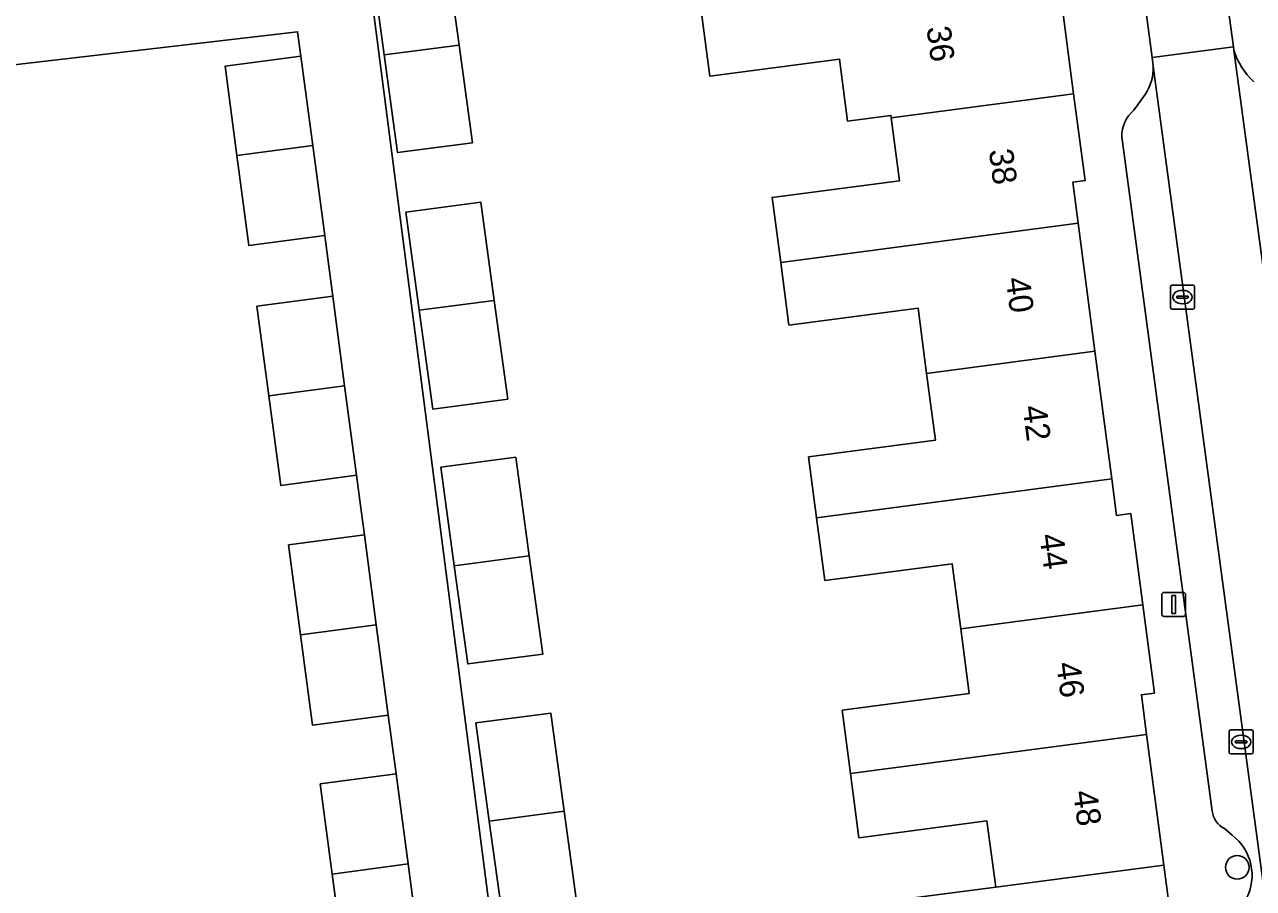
# Model space of a CAD drawing. Extents: x 163147 to 163550, y 380933 to 381639.
# Drawn here: x 163359.7 to 163410.6, y 381335.7 to 381371.5 of the extents above; entities that cross this region are included whole.
import ezdxf

# ---------------------------------------------------------------- set-up
doc = ezdxf.new("R2010")
doc.units = 0
for name, color, linetype in [('IMGEO_Boom', 7, 'Continuous'), ('IMGEO_Erf', 7, 'Continuous'), ('IMGEO_Kolk', 7, 'Continuous'), ('IMGEO_Lichtmast', 7, 'Continuous'), ('IMGEO_Pand', 7, 'Continuous'), ('IMGEO_Pand_nummerreeks', 7, 'Continuous'), ('IMGEO_Parkeervlak_open', 7, 'Continuous'), ('IMGEO_Rijbaan_lokaal_open', 7, 'Continuous'), ('IMGEO_Voetpad_open', 7, 'Continuous')]:
    doc.layers.add(name, color=color, linetype=linetype)

msp = doc.modelspace()

# ---------------------------------------------------------------- linework, layer by layer
at = {"layer": 'IMGEO_Boom'}
msp.add_circle((163409.946, 381336.541), 0.489, dxfattribs=at)
at = {"layer": 'IMGEO_Erf'}
for points in [[(163373.686, 381375.541), (163379.182, 381333.036)], [(163382.784, 381333.502), (163399.932, 381335.719), (163399.572, 381338.463), (163394.265, 381337.766), (163393.915, 381340.431), (163393.57, 381343.051), (163398.835, 381343.744), (163398.483, 381346.421), (163398.129, 381349.112), (163392.852, 381348.418), (163392.51, 381351.018), (163392.178, 381353.546), (163397.432, 381354.237), (163397.068, 381357.007), (163396.713, 381359.709), (163391.363, 381359.005), (163391.022, 381361.596), (163390.667, 381364.294), (163395.947, 381364.988), (163395.605, 381367.589), (163395.591, 381367.696), (163393.795, 381367.46), (163393.457, 381370.029), (163388.079, 381369.322), (163387.736, 381371.936)], [(163372.924, 381332.563), (163372.433, 381336.262), (163371.937, 381339.995), (163375.08, 381340.413), (163374.918, 381341.632), (163374.756, 381342.85), (163371.613, 381342.432), (163371.118, 381346.167), (163370.622, 381349.899), (163373.765, 381350.318), (163373.603, 381351.536), (163373.438, 381352.782), (163370.295, 381352.363), (163369.803, 381356.07), (163369.309, 381359.787), (163372.452, 381360.205), (163372.288, 381361.442), (163372.119, 381362.716), (163368.976, 381362.298), (163368.48, 381366.03), (163367.988, 381369.734), (163371.131, 381370.151), (163370.998, 381371.159), (163352.337, 381368.984)]]:
    msp.add_lwpolyline(points, dxfattribs=at)
for points in [[(163377.694, 381370.61), (163378.249, 381366.564), (163375.142, 381366.154), (163374.587, 381370.2), (163374.056, 381374.068), (163377.161, 381374.494)], [(163379.146, 381360.028), (163379.707, 381355.941), (163376.6, 381355.53), (163376.039, 381359.618), (163375.481, 381363.683), (163378.588, 381364.093)], [(163380.598, 381349.444), (163381.155, 381345.378), (163378.049, 381344.968), (163377.491, 381349.033), (163376.93, 381353.119), (163380.037, 381353.53)], [(163378.942, 381338.454), (163378.383, 381342.525), (163381.49, 381342.935), (163382.049, 381338.865), (163382.685, 381334.223), (163379.58, 381333.797)]]:
    msp.add_lwpolyline(points, close=True, dxfattribs=at)
at = {"layer": 'IMGEO_Kolk'}
for p, q in [((163407.177, 381359.739), (163407.177, 381360.591)), ((163407.252, 381360.665), (163408.104, 381360.665)), ((163407.665, 381360.445), (163407.69, 381360.445)), ((163408.178, 381360.591), (163408.178, 381359.739)), ((163407.436, 381360.159), (163407.436, 381360.171)), ((163407.874, 381360.122), (163407.476, 381360.122)), ((163407.479, 381360.208), (163407.877, 381360.208)), ((163407.688, 381359.885), (163407.663, 381359.885)), ((163407.92, 381360.171), (163407.92, 381360.159)), ((163408.104, 381359.665), (163407.252, 381359.665)), ((163409.606, 381341.311), (163409.606, 381342.163)), ((163409.681, 381342.237), (163410.533, 381342.237)), ((163410.094, 381342.017), (163410.119, 381342.017)), ((163410.607, 381342.163), (163410.607, 381341.311)), ((163409.865, 381341.731), (163409.865, 381341.743)), ((163410.303, 381341.694), (163409.905, 381341.694)), ((163409.908, 381341.78), (163410.306, 381341.78)), ((163410.117, 381341.457), (163410.092, 381341.457)), ((163410.349, 381341.743), (163410.349, 381341.731)), ((163410.533, 381341.237), (163409.681, 381341.237))]:
    msp.add_line(p, q, dxfattribs=at)
for points in [[(163407.177, 381359.739), (163407.177, 381360.591)], [(163407.252, 381360.665), (163408.104, 381360.665)], [(163408.178, 381360.591), (163408.178, 381359.739)], [(163408.104, 381359.665), (163407.252, 381359.665)], [(163409.606, 381341.311), (163409.606, 381342.163)], [(163409.681, 381342.237), (163410.533, 381342.237)], [(163410.607, 381342.163), (163410.607, 381341.311)], [(163410.533, 381341.237), (163409.681, 381341.237)]]:
    msp.add_lwpolyline(points, dxfattribs=at)
for centre, radius, start, end in [((163407.254, 381360.589), 0.0765, 91.552, 178.448), ((163407.254, 381360.589), 0.0765, 91.552, 178.448), ((163408.102, 381360.589), 0.0765, 1.552, 88.448), ((163408.102, 381360.589), 0.0765, 1.552, 88.448), ((163407.254, 381359.741), 0.0765, 181.552, 268.448), ((163407.254, 381359.741), 0.0765, 181.552, 268.448), ((163407.476, 381360.168), 0.0403, 85.8775, 175.7526), ((163407.473, 381360.158), 0.0366, 178.938, 274.7102), ((163407.877, 381360.165), 0.043, 264.8664, 352.4533), ((163407.881, 381360.17), 0.0386, 1.7309, 96.639), ((163408.102, 381359.741), 0.0765, 271.552, 358.448), ((163408.102, 381359.741), 0.0765, 271.552, 358.448), ((163409.683, 381342.161), 0.0765, 91.552, 178.448), ((163409.683, 381342.161), 0.0765, 91.552, 178.448), ((163410.531, 381342.161), 0.0765, 1.552, 88.448), ((163410.531, 381342.161), 0.0765, 1.552, 88.448), ((163409.905, 381341.74), 0.0403, 85.8775, 175.7526), ((163409.902, 381341.73), 0.0366, 178.938, 274.7102), ((163410.306, 381341.737), 0.043, 264.8664, 352.4533), ((163410.31, 381341.742), 0.0386, 1.7309, 96.639), ((163409.683, 381341.313), 0.0765, 181.552, 268.448), ((163409.683, 381341.313), 0.0765, 181.552, 268.448), ((163410.531, 381341.313), 0.0765, 271.552, 358.448), ((163410.531, 381341.313), 0.0765, 271.552, 358.448)]:
    msp.add_arc(centre, radius, start, end, dxfattribs=at)
for centre, major_axis, ratio, start_param, end_param in [((163407.664, 381360.165), (-0.387, 0.002), 0.722429, 4.712389, 7.853982), ((163407.689, 381360.165), (-0.39, 0.002), 0.717154, 1.570796, 4.712389), ((163410.093, 381341.737), (-0.387, 0.002), 0.722429, 4.712389, 7.853982), ((163410.118, 381341.737), (-0.39, 0.002), 0.717154, 1.570796, 4.712389)]:
    msp.add_ellipse(centre, major_axis=major_axis, ratio=ratio, start_param=start_param, end_param=end_param, dxfattribs=at)
at = {"layer": 'IMGEO_Lichtmast'}
for p, q in [((163406.816, 381347.034), (163406.816, 381347.834)), ((163406.816, 381347.834), (163406.816, 381347.034)), ((163406.916, 381347.934), (163407.706, 381347.934)), ((163407.706, 381347.934), (163406.916, 381347.934)), ((163407.806, 381347.834), (163407.806, 381347.034)), ((163407.806, 381347.034), (163407.806, 381347.834)), ((163407.706, 381346.934), (163406.916, 381346.934)), ((163406.916, 381346.934), (163407.706, 381346.934))]:
    msp.add_line(p, q, dxfattribs=at)
msp.add_lwpolyline([(163407.236, 381347.809), (163407.386, 381347.809), (163407.386, 381347.059), (163407.236, 381347.059), (163407.236, 381347.809)], dxfattribs=at)
for centre, start, end in [((163406.916, 381347.834), 90, 180), ((163406.916, 381347.834), 90, 180), ((163407.706, 381347.834), 0, 90), ((163407.706, 381347.834), 360, 90), ((163406.916, 381347.034), 180, 270), ((163406.916, 381347.034), 180, 270), ((163407.706, 381347.034), 270, 0), ((163407.706, 381347.034), 270, 0)]:
    msp.add_arc(centre, 0.1, start, end, dxfattribs=at)
at = {"layer": 'IMGEO_Pand'}
for points in [[(163374.587, 381370.2), (163377.694, 381370.61), (163377.161, 381374.494), (163374.056, 381374.068)], [(163387.736, 381371.936), (163388.079, 381369.322), (163393.457, 381370.029), (163393.795, 381367.46), (163395.591, 381367.696), (163395.605, 381367.589), (163403.164, 381368.587), (163402.674, 381372.311), (163400.282, 381371.997), (163400.076, 381373.565)], [(163377.694, 381370.61), (163374.587, 381370.2), (163375.142, 381366.154), (163378.249, 381366.564)], [(163371.131, 381370.151), (163367.988, 381369.734), (163368.48, 381366.03), (163371.623, 381366.449)], [(163391.022, 381361.596), (163403.353, 381363.224), (163403.129, 381364.925), (163403.637, 381364.992), (163403.164, 381368.587), (163395.605, 381367.589), (163395.947, 381364.988), (163390.667, 381364.294)], [(163371.623, 381366.449), (163368.48, 381366.03), (163368.976, 381362.298), (163372.119, 381362.716)], [(163376.039, 381359.618), (163379.146, 381360.028), (163378.588, 381364.093), (163375.481, 381363.683)], [(163404.049, 381357.929), (163403.353, 381363.224), (163391.022, 381361.596), (163391.363, 381359.005), (163396.713, 381359.709), (163397.068, 381357.007)], [(163372.452, 381360.205), (163369.309, 381359.787), (163369.803, 381356.07), (163372.945, 381356.489)], [(163379.146, 381360.028), (163376.039, 381359.618), (163376.6, 381355.53), (163379.707, 381355.941)], [(163404.049, 381357.929), (163397.068, 381357.007), (163397.432, 381354.237), (163392.178, 381353.546), (163392.51, 381351.018), (163404.745, 381352.635)], [(163372.945, 381356.489), (163369.803, 381356.07), (163370.295, 381352.363), (163373.438, 381352.782)], [(163377.491, 381349.033), (163380.598, 381349.444), (163380.037, 381353.53), (163376.93, 381353.119)], [(163398.483, 381346.421), (163406.03, 381347.417), (163405.533, 381351.2), (163404.944, 381351.123), (163404.745, 381352.635), (163392.51, 381351.018), (163392.852, 381348.418), (163398.129, 381349.112)], [(163373.765, 381350.318), (163370.622, 381349.899), (163371.118, 381346.167), (163374.26, 381346.586)], [(163380.598, 381349.444), (163377.491, 381349.033), (163378.049, 381344.968), (163381.155, 381345.378)], [(163398.483, 381346.421), (163398.835, 381343.744), (163393.57, 381343.051), (163393.915, 381340.431), (163406.187, 381342.051), (163405.971, 381343.69), (163406.511, 381343.761), (163406.03, 381347.417)], [(163374.26, 381346.586), (163371.118, 381346.167), (163371.613, 381342.432), (163374.756, 381342.85)], [(163378.942, 381338.454), (163382.049, 381338.865), (163381.49, 381342.935), (163378.383, 381342.525)], [(163406.187, 381342.051), (163393.915, 381340.431), (163394.265, 381337.766), (163399.572, 381338.463), (163399.932, 381335.719), (163401.942, 381335.983), (163406.899, 381336.635)], [(163375.08, 381340.413), (163371.937, 381339.995), (163372.433, 381336.262), (163375.575, 381336.681)], [(163382.049, 381338.865), (163378.942, 381338.454), (163379.58, 381333.797), (163382.685, 381334.223)], [(163375.575, 381336.681), (163372.433, 381336.262), (163372.924, 381332.563), (163376.067, 381332.981)]]:
    msp.add_lwpolyline(points, close=True, dxfattribs=at)
at = {"layer": 'IMGEO_Parkeervlak_open'}
for points in [[(163409.808, 381370.393), (163417.023, 381316.959), (163417.13, 381316.166)], [(163412.274, 381317.247), (163413.073, 381316.642), (163413.31, 381316.453), (163413.709, 381315.897), (163413.628, 381316.496), (163406.464, 381369.736)], [(163406.129, 381368.567), (163405.657, 381367.909)], [(163405.157, 381366.806), (163408.907, 381338.869)], [(163409.412, 381338.143), (163409.728, 381337.875)]]:
    msp.add_lwpolyline(points, dxfattribs=at)
for centre, radius, start, end in [((163412.754, 381371.321), 3.089, 197.4756, 226.4724), ((163404.538, 381369.655), 1.927, 325.6202, 2.3984), ((163406.583, 381366.824), 1.426, 130.4883, 180.7413), ((163409.852, 381338.988), 0.952, 187.157, 242.4873), ((163408.485, 381336.213), 2.075, 331.7558, 53.1962)]:
    msp.add_arc(centre, radius, start, end, dxfattribs=at)
at = {"layer": 'IMGEO_Rijbaan_lokaal_open'}
for points in [[(163409.423, 381373.262), (163406.059, 381372.796), (163406.417, 381370.092), (163409.789, 381370.536)], [(163413.628, 381316.496), (163417.023, 381316.959), (163409.808, 381370.393), (163409.789, 381370.536), (163406.417, 381370.092), (163406.464, 381369.736)]]:
    msp.add_lwpolyline(points, close=True, dxfattribs=at)
at = {"layer": 'IMGEO_Voetpad_open'}
for points in [[(163379.182, 381333.036), (163373.686, 381375.541), (163392.431, 381378.067), (163394.407, 381378.327), (163399.364, 381378.978), (163399.159, 381380.49), (163394.204, 381379.827), (163392.162, 381379.554), (163386.909, 381378.852), (163376.889, 381377.496), (163373.783, 381377.077), (163373.493, 381377.038), (163367.775, 381419.465)], [(163408.974, 381376.615), (163409.423, 381373.262), (163409.789, 381370.536), (163409.808, 381370.393)], [(163406.464, 381369.736), (163406.417, 381370.092), (163406.059, 381372.796)], [(163402.674, 381372.311), (163403.164, 381368.587), (163403.637, 381364.992), (163403.129, 381364.925), (163403.353, 381363.224), (163404.049, 381357.929), (163404.745, 381352.635), (163404.944, 381351.123), (163405.533, 381351.2), (163406.03, 381347.417), (163406.511, 381343.761), (163405.971, 381343.69), (163406.187, 381342.051), (163406.899, 381336.635), (163407.09, 381335.16)], [(163352.337, 381368.984), (163370.998, 381371.159), (163371.131, 381370.151), (163371.623, 381366.449), (163372.119, 381362.716), (163372.288, 381361.442), (163372.452, 381360.205), (163372.945, 381356.489), (163373.438, 381352.782), (163373.603, 381351.536), (163373.765, 381350.318), (163374.26, 381346.586), (163374.756, 381342.85), (163374.918, 381341.632), (163375.08, 381340.413), (163375.575, 381336.681), (163376.067, 381332.981), (163376.227, 381331.775), (163376.249, 381331.604), (163355.814, 381328.888)], [(163405.657, 381367.909), (163406.129, 381368.567)], [(163408.907, 381338.869), (163405.157, 381366.806)], [(163409.728, 381337.875), (163409.412, 381338.143)], [(163407.09, 381335.16), (163406.899, 381336.635), (163401.942, 381335.983), (163399.932, 381335.719), (163382.784, 381333.502)]]:
    msp.add_lwpolyline(points, dxfattribs=at)
for centre, radius, start, end in [((163412.754, 381371.321), 3.089, 197.4756, 226.4724), ((163404.538, 381369.655), 1.927, 325.6202, 2.3984), ((163406.583, 381366.824), 1.426, 130.4883, 180.7413), ((163409.852, 381338.988), 0.952, 187.157, 242.4873), ((163408.485, 381336.213), 2.075, 331.7558, 53.1962)]:
    msp.add_arc(centre, radius, start, end, dxfattribs=at)

# ---------------------------------------------------------------- texts
at = {"layer": 'IMGEO_Pand_nummerreeks'}
for s, rotation, p in [('36', 277.4914, (163397.061, 381371.339)), ('38', 277.4916, (163399.646, 381366.251)), ('40', 277.4916, (163400.345, 381360.935)), ('42', 277.4916, (163401.043, 381355.626)), ('44', 277.4916, (163401.743, 381350.308)), ('46', 277.4916, (163402.442, 381344.992)), ('48', 277.4916, (163403.141, 381339.674))]:
    msp.add_text(s, height=1, rotation=rotation, dxfattribs=at).set_placement(p)

doc.saveas('drawing.dxf')
